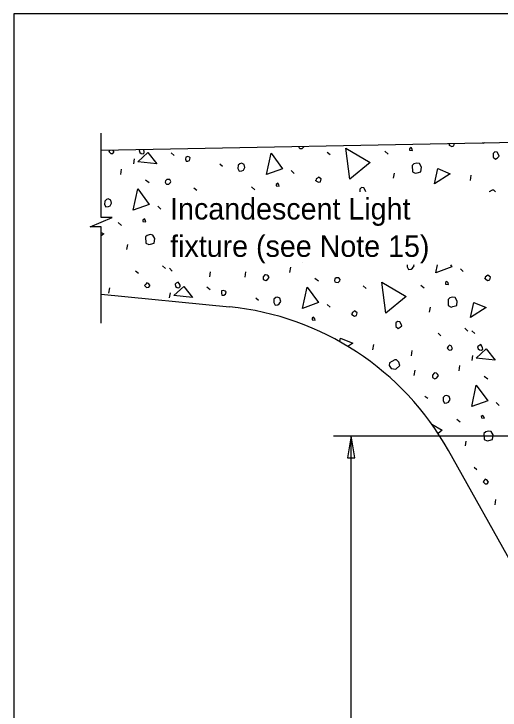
# Model space of a CAD drawing. Extents: x 112544 to 112597.1, y 111084 to 111107.1.
# Drawn here: x 112543.992 to 112547.426, y 111100.441 to 111105.363 of the extents above; entities that cross this region are included whole.
import ezdxf

# ---------------------------------------------------------------- set-up
doc = ezdxf.new("R2010")
doc.units = 0
for name, color, linetype in [('ActivePts-ConstElements', 7, 'Continuous'), ('Dimension', 7, 'Continuous'), ('Miscellaneous', 7, 'Continuous'), ('SupstrConc', 7, 'Continuous')]:
    doc.layers.add(name, color=color, linetype=linetype)

msp = doc.modelspace()

# ---------------------------------------------------------------- linework, layer by layer
at = {"layer": 'ActivePts-ConstElements'}
msp.add_lwpolyline([(112543.9918, 111085.9039), (112574.7797, 111085.9039), (112574.7797, 111105.3634), (112543.9918, 111105.3634)], close=True, dxfattribs=at)
at = {"layer": 'Dimension'}
for p, q in [((112546.25, 111102.3807), (112548.1294, 111102.3807)), ((112546.3736, 111096.6779), (112546.3736, 111102.3807))]:
    msp.add_line(p, q, dxfattribs=at)
msp.add_lwpolyline([(112544.6086, 111103.1768), (112544.6086, 111103.8573), (112544.5311, 111103.8573), (112544.6086, 111103.891), (112544.6861, 111103.9248), (112544.6086, 111103.9248), (112544.6086, 111104.5204)], dxfattribs=at)
msp.add_lwpolyline([(112546.3735, 111102.3806), (112546.3471, 111102.2244), (112546.4, 111102.2244)], close=True, dxfattribs=at)
at = {"layer": 'Miscellaneous'}
for p, q in [((112545.8886, 111104.4246), (112545.8895, 111104.4239)), ((112545.1013, 111104.3809), (112545.1247, 111104.3613)), ((112546.2049, 111104.3868), (112546.2252, 111104.3689)), ((112546.6123, 111104.3924), (112546.6357, 111104.3728)), ((112544.8376, 111104.3025), (112544.8437, 111104.3378)), ((112545.4459, 111104.3024), (112545.4655, 111104.287)), ((112544.7461, 111104.2288), (112544.7515, 111104.2665)), ((112545.95, 111104.2563), (112545.9709, 111104.2361)), ((112546.6737, 111104.2018), (112546.6798, 111104.2371)), ((112547.2161, 111104.1867), (112547.2216, 111104.2244)), ((112544.922, 111104.1905), (112544.9478, 111104.1716)), ((112545.2631, 111104.1344), (112545.2834, 111104.1166)), ((112545.6705, 111104.1401), (112545.6939, 111104.1204)), ((112545.0082, 111104.004), (112545.0291, 111103.9837)), ((112544.7288, 111103.8877), (112544.7521, 111103.8681)), ((112544.7902, 111103.6971), (112544.7963, 111103.7324)), ((112545.0407, 111103.5831), (112545.0617, 111103.5628)), ((112545.0896, 111103.5651), (112545.1105, 111103.5448)), ((112545.9415, 111103.5346), (112545.9469, 111103.5722)), ((112546.033, 111103.6083), (112546.0331, 111103.6084)), ((112544.8509, 111103.5477), (112544.8712, 111103.5299)), ((112545.375, 111103.5044), (112545.3811, 111103.5397)), ((112545.6243, 111103.5013), (112545.6297, 111103.539)), ((112547.1454, 111103.5621), (112547.1663, 111103.5418)), ((112546.1174, 111103.4963), (112546.1432, 111103.4773)), ((112544.6632, 111103.3887), (112544.6686, 111103.4264)), ((112545.3549, 111103.4343), (112545.3783, 111103.4147)), ((112546.4585, 111103.4402), (112546.4789, 111103.4223)), ((112546.866, 111103.4458), (112546.8893, 111103.4262)), ((112545.0913, 111103.3559), (112545.0973, 111103.3912)), ((112545.6995, 111103.3558), (112545.7192, 111103.3404)), ((112546.2036, 111103.3097), (112546.2246, 111103.2895)), ((112546.9274, 111103.2552), (112546.9335, 111103.2905)), ((112547.1779, 111103.1412), (112547.1989, 111103.1209)), ((112547.2268, 111103.1232), (112547.2477, 111103.1029)), ((112546.9881, 111103.1058), (112547.0084, 111103.088)), ((112546.528, 111102.9877), (112546.5334, 111103.0254)), ((112546.8004, 111102.9468), (112546.8058, 111102.9845)), ((112547.2285, 111102.914), (112547.2345, 111102.9493)), ((112547.1369, 111102.8403), (112547.1423, 111102.878)), ((112546.8197, 111102.8071), (112546.8251, 111102.8448)), ((112547.3128, 111102.802), (112547.3386, 111102.783)), ((112546.8949, 111102.6616), (112546.9146, 111102.6461)), ((112547.399, 111102.6155), (112547.42, 111102.5952)), ((112547.1196, 111102.4992), (112547.143, 111102.4796)), ((112547.181, 111102.3086), (112547.1871, 111102.3439)), ((112547.2418, 111102.1592), (112547.2621, 111102.1414)), ((112547.3906, 111101.8937), (112547.396, 111101.9314))]:
    msp.add_line(p, q, dxfattribs=at)
for points in [[(112547.0664, 111104.4364), (112547.0848, 111104.4258), (112547.0993, 111104.4297), (112547.1043, 111104.449)], [(112547.307, 111104.4465), (112547.3062, 111104.453)], [(112547.315, 111104.4532), (112547.307, 111104.4465)], [(112544.6615, 111104.3899), (112544.6757, 111104.3756), (112544.6908, 111104.3771), (112544.6985, 111104.3869), (112544.6972, 111104.3917), (112544.6913, 111104.4007)], [(112544.6696, 111104.4003), (112544.6692, 111104.3997), (112544.6615, 111104.3899)], [(112544.8836, 111104.4045), (112544.8766, 111104.3984), (112544.8805, 111104.3839)], [(112544.8805, 111104.3839), (112544.8903, 111104.3762), (112544.9037, 111104.3746), (112544.9121, 111104.382), (112544.9119, 111104.3923), (112544.9063, 111104.4037), (112544.9053, 111104.405)], [(112546.0031, 111104.4269), (112546.0029, 111104.4258), (112546.0055, 111104.4162)], [(112546.0055, 111104.4162), (112546.0116, 111104.4126), (112546.0274, 111104.4117), (112546.0399, 111104.4228), (112546.0416, 111104.4277)], [(112546.3652, 111104.1942), (112546.3372, 111104.4145), (112546.5093, 111104.3131), (112546.3652, 111104.1942)], [(112546.7862, 111104.4002), (112546.8075, 111104.3981), (112546.8049, 111104.4078), (112546.7968, 111104.4186), (112546.7861, 111104.4105), (112546.7862, 111104.4002)], [(112547.0678, 111104.4482), (112547.0664, 111104.4364), (112547.0651, 111104.4413)], [(112544.8671, 111104.3182), (112544.9375, 111104.3836), (112545.0001, 111104.3046), (112544.8671, 111104.3182)], [(112545.2039, 111104.336), (112545.2078, 111104.3215), (112545.2205, 111104.3223), (112545.232, 111104.328), (112545.2377, 111104.345), (112545.231, 111104.351), (112545.2194, 111104.3556), (112545.2049, 111104.3518), (112545.2039, 111104.336)], [(112545.7764, 111104.228), (112545.8084, 111104.3789), (112545.8897, 111104.2687), (112545.7764, 111104.228)], [(112547.3768, 111104.3695), (112547.3765, 111104.3513), (112547.3931, 111104.3376), (112547.4087, 111104.347), (112547.4188, 111104.3575), (112547.4156, 111104.3695), (112547.4063, 111104.3851), (112547.3898, 111104.3885), (112547.3773, 111104.3774), (112547.3768, 111104.3695)], [(112545.5752, 111104.2931), (112545.5738, 111104.2694), (112545.5838, 111104.2514), (112545.6013, 111104.2535), (112545.6127, 111104.2592), (112545.6234, 111104.2775), (112545.6175, 111104.2993), (112545.5998, 111104.3075), (112545.5877, 111104.3042), (112545.5752, 111104.2931)], [(112546.805, 111104.2913), (112546.8064, 111104.2477), (112546.8272, 111104.2377), (112546.8392, 111104.241), (112546.8658, 111104.2481), (112546.8701, 111104.2803), (112546.8558, 111104.3049), (112546.8369, 111104.3076), (112546.8176, 111104.3025), (112546.805, 111104.2913)], [(112546.9637, 111104.163), (112546.9867, 111104.2701), (112547.074, 111104.234), (112546.9637, 111104.163)], [(112546.1246, 111104.1841), (112546.143, 111104.1735), (112546.1575, 111104.1774), (112546.1626, 111104.1969), (112546.1436, 111104.2099), (112546.1352, 111104.2025), (112546.1262, 111104.1975), (112546.1246, 111104.1841), (112546.1233, 111104.1889)], [(112545.0637, 111104.1638), (112545.0698, 111104.1603), (112545.0856, 111104.1593), (112545.0982, 111104.1705), (112545.1011, 111104.179), (112545.0923, 111104.1922), (112545.0717, 111104.1918), (112545.0634, 111104.1844), (112545.0611, 111104.1735), (112545.0637, 111104.1638)], [(112545.8445, 111104.1478), (112545.8657, 111104.1458), (112545.8631, 111104.1554), (112545.8551, 111104.1662), (112545.8443, 111104.1581), (112545.8445, 111104.1478)], [(112544.8346, 111103.9756), (112544.8666, 111104.1265), (112544.9479, 111104.0163), (112544.8346, 111103.9756)], [(112546.435, 111104.1171), (112546.4348, 111104.1057)], [(112546.4769, 111104.1057), (112546.4738, 111104.1172), (112546.4645, 111104.1328), (112546.448, 111104.1362), (112546.4355, 111104.125), (112546.435, 111104.1171)], [(112547.3947, 111104.1057), (112547.3823, 111104.1173), (112547.3695, 111104.1165), (112547.3491, 111104.1058), (112547.3489, 111104.1057)], [(112544.6334, 111104.0407), (112544.632, 111104.0171), (112544.642, 111103.999), (112544.6595, 111104.0012), (112544.671, 111104.0068), (112544.6816, 111104.0252), (112544.6758, 111104.0469), (112544.658, 111104.0551), (112544.646, 111104.0519), (112544.6334, 111104.0407)], [(112544.9027, 111103.8955), (112544.9239, 111103.8934), (112544.9213, 111103.9031), (112544.9133, 111103.9139), (112544.9025, 111103.9058), (112544.9027, 111103.8955)], [(112544.6086, 111103.8185), (112544.6258, 111103.8084), (112544.6086, 111103.7942)], [(112544.9215, 111103.7866), (112544.9228, 111103.743), (112544.9436, 111103.733), (112544.9557, 111103.7363), (112544.9823, 111103.7434), (112544.9866, 111103.7756), (112544.9722, 111103.8002), (112544.9534, 111103.803), (112544.934, 111103.7978), (112544.9215, 111103.7866)], [(112546.77, 111103.5883), (112546.7692, 111103.5752), (112546.7792, 111103.5571), (112546.7967, 111103.5593), (112546.8082, 111103.5649), (112546.8188, 111103.5833), (112546.8174, 111103.5883)], [(112546.9718, 111103.5337), (112546.9834, 111103.5883)], [(112547.0749, 111103.5883), (112547.0851, 111103.5744), (112546.9718, 111103.5337)], [(112545.7528, 111103.5047), (112545.7525, 111103.4865), (112545.7702, 111103.4783), (112545.7841, 111103.4846), (112545.7953, 111103.5006), (112545.7872, 111103.5113), (112545.7805, 111103.5173), (112545.7695, 111103.5195), (112545.7647, 111103.5182), (112545.7528, 111103.5047)], [(112547.32, 111103.4898), (112547.3384, 111103.4792), (112547.3529, 111103.4831), (112547.358, 111103.5026), (112547.339, 111103.5156), (112547.3306, 111103.5082), (112547.3216, 111103.5032), (112547.32, 111103.4898), (112547.3187, 111103.4947)], [(112545.1342, 111103.4373), (112545.144, 111103.4296), (112545.1574, 111103.428), (112545.1657, 111103.4354), (112545.1655, 111103.4457), (112545.1599, 111103.4571), (112545.1518, 111103.4679), (112545.1386, 111103.4592), (112545.1303, 111103.4518), (112545.1342, 111103.4373)], [(112546.2591, 111103.4696), (112546.2653, 111103.466), (112546.281, 111103.4651), (112546.2936, 111103.4762), (112546.2965, 111103.4847), (112546.2878, 111103.4979), (112546.2672, 111103.4976), (112546.2588, 111103.4902), (112546.2565, 111103.4792), (112546.2591, 111103.4696)], [(112546.6188, 111103.2476), (112546.5909, 111103.4679), (112546.763, 111103.3664), (112546.6188, 111103.2476)], [(112547.0399, 111103.4536), (112547.0611, 111103.4515), (112547.0585, 111103.4612), (112547.0505, 111103.4719), (112547.0397, 111103.4639), (112547.0399, 111103.4536)], [(112544.9151, 111103.4433), (112544.9293, 111103.429), (112544.9445, 111103.4305), (112544.9522, 111103.4403), (112544.9509, 111103.4451), (112544.9422, 111103.4583), (112544.9306, 111103.463), (112544.9229, 111103.4531), (112544.9151, 111103.4433)], [(112545.1207, 111103.3716), (112545.1912, 111103.437), (112545.2537, 111103.358), (112545.1207, 111103.3716)], [(112546.03, 111103.2813), (112546.0621, 111103.4323), (112546.1434, 111103.3221), (112546.03, 111103.2813)], [(112545.4576, 111103.3894), (112545.4615, 111103.3749), (112545.4742, 111103.3757), (112545.4856, 111103.3813), (112545.4914, 111103.3984), (112545.4846, 111103.4044), (112545.473, 111103.409), (112545.4585, 111103.4051), (112545.4576, 111103.3894)], [(112545.8288, 111103.3465), (112545.8274, 111103.3228), (112545.8374, 111103.3048), (112545.855, 111103.3069), (112545.8664, 111103.3126), (112545.877, 111103.3309), (112545.8712, 111103.3527), (112545.8534, 111103.3608), (112545.8414, 111103.3576), (112545.8288, 111103.3465)], [(112547.0587, 111103.3447), (112547.06, 111103.3011), (112547.0808, 111103.2911), (112547.0929, 111103.2944), (112547.1194, 111103.3015), (112547.1238, 111103.3337), (112547.1094, 111103.3583), (112547.0906, 111103.361), (112547.0712, 111103.3559), (112547.0587, 111103.3447)], [(112547.2173, 111103.2164), (112547.2404, 111103.3235), (112547.3277, 111103.2874), (112547.2173, 111103.2164)], [(112546.0981, 111103.2012), (112546.1194, 111103.1992), (112546.1168, 111103.2088), (112546.1087, 111103.2196), (112546.0979, 111103.2115), (112546.0981, 111103.2012)], [(112546.3783, 111103.2375), (112546.3966, 111103.2269), (112546.4111, 111103.2308), (112546.4163, 111103.2502), (112546.3972, 111103.2633), (112546.3889, 111103.2558), (112546.3799, 111103.2508), (112546.3783, 111103.2375), (112546.377, 111103.2423)], [(112546.6887, 111103.1705), (112546.6884, 111103.1523), (112546.705, 111103.1387), (112546.7206, 111103.148), (112546.7307, 111103.1585), (112546.7275, 111103.1706), (112546.7181, 111103.1862), (112546.7017, 111103.1896), (112546.6891, 111103.1784), (112546.6887, 111103.1705)], [(112546.2933, 111103.0464), (112546.2986, 111103.0712), (112546.3859, 111103.0351), (112546.3511, 111103.0127)], [(112547.2714, 111102.9954), (112547.2812, 111102.9877), (112547.2946, 111102.9861), (112547.3029, 111102.9935), (112547.3027, 111103.0038), (112547.2971, 111103.0152), (112547.289, 111103.026), (112547.2758, 111103.0173), (112547.2675, 111103.0099), (112547.2714, 111102.9954)], [(112547.0523, 111103.0014), (112547.0665, 111102.9871), (112547.0817, 111102.9885), (112547.0894, 111102.9984), (112547.0881, 111103.0032), (112547.0794, 111103.0164), (112547.0678, 111103.0211), (112547.0601, 111103.0112), (112547.0523, 111103.0014)], [(112547.2579, 111102.9297), (112547.3284, 111102.9951), (112547.3909, 111102.9161), (112547.2579, 111102.9297)], [(112546.6426, 111102.8787), (112546.6564, 111102.8565), (112546.6886, 111102.8522), (112546.7178, 111102.8781), (112546.7114, 111102.9023), (112546.6941, 111102.9184), (112546.6814, 111102.9175), (112546.661, 111102.9069), (112546.6454, 111102.8975), (112546.6426, 111102.8787)], [(112546.9482, 111102.8104), (112546.9479, 111102.7922), (112546.9656, 111102.784), (112546.9795, 111102.7903), (112546.9907, 111102.8063), (112546.9827, 111102.8171), (112546.9759, 111102.823), (112546.9649, 111102.8253), (112546.9601, 111102.824), (112546.9482, 111102.8104)], [(112547.2255, 111102.5871), (112547.2575, 111102.738), (112547.3388, 111102.6278), (112547.2255, 111102.5871)], [(112547.0242, 111102.6522), (112547.0228, 111102.6286), (112547.0328, 111102.6105), (112547.0504, 111102.6126), (112547.0618, 111102.6183), (112547.0724, 111102.6367), (112547.0666, 111102.6584), (112547.0489, 111102.6666), (112547.0368, 111102.6634), (112547.0242, 111102.6522)], [(112547.2935, 111102.507), (112547.3148, 111102.5049), (112547.3122, 111102.5146), (112547.3041, 111102.5253), (112547.2933, 111102.5173), (112547.2935, 111102.507)], [(112546.9434, 111102.463), (112547.0166, 111102.4198), (112546.9886, 111102.3967)], [(112547.3123, 111102.3981), (112547.3137, 111102.3545), (112547.3345, 111102.3445), (112547.3465, 111102.3478), (112547.3731, 111102.3549), (112547.3774, 111102.3871), (112547.363, 111102.4117), (112547.3442, 111102.4144), (112547.3249, 111102.4093), (112547.3123, 111102.3981)], [(112547.306, 111102.0548), (112547.3202, 111102.0405), (112547.3353, 111102.0419), (112547.343, 111102.0518), (112547.3417, 111102.0566), (112547.333, 111102.0698), (112547.3214, 111102.0745), (112547.3137, 111102.0646), (112547.306, 111102.0548)]]:
    msp.add_lwpolyline(points, dxfattribs=at)
at = {"layer": 'SupstrConc'}
for p, q in [((112544.6086, 111104.3991), (112554.7971, 111104.6028)), ((112544.6086, 111103.383), (112545.5144, 111103.2921)), ((112550.511, 111096.0946), (112547.0612, 111102.2767))]:
    msp.add_line(p, q, dxfattribs=at)
msp.add_arc((112545.3148, 111101.3021), 2, 29.163, 84.2698, dxfattribs=at)

# ---------------------------------------------------------------- texts
at = {"layer": 'Dimension'}
for s, p in [('Incandescent Light', (112545.0952, 111103.9098)), ('fixture (see Note 15)', (112545.0952, 111103.6458))]:
    msp.add_text(s, height=0.1512, dxfattribs=at).set_placement(p)

doc.saveas('drawing.dxf')
